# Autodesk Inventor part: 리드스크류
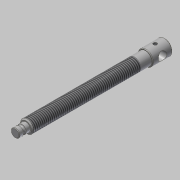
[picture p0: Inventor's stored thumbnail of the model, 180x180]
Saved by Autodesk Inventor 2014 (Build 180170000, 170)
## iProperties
Created: 2019-04
Part Number: 리드스크류
Material: 강철, 연강
Document SubType Name: Modeling
Designer: mduedu
Density: 1 g/cm^3
Appearance: 강철
Author: mduedu
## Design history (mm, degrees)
sketch "스케치1"
  geometry: C1 r 6 at (0, 0); 1 further point
  constraints: 1 centre point, 1 coincident
  dimensions: "d0" = 12 diameter of C1
extrude "돌출1" new body sketch "스케치1" distance "d1" = 110; taper "d2" = 0 deg
sketch "스케치2"
  geometry: C1 r 4 at (0, 0); 1 further point
  constraints: 1 centre point, 1 coincident
  dimensions: "d3" = 8 diameter of C1
extrude "돌출2" join sketch "스케치2" distance "d4" = 10; taper "d5" = 0 deg
sketch "스케치3"
  geometry: C1 r 7 at (0, 0); 1 further point
  constraints: 1 centre point, 1 coincident
  dimensions: "d9" = 14 diameter of C1
extrude "돌출3" join sketch "스케치3" distance "d10" = 18; taper "d11" = 0 deg
feature "스레드1" dims "d12" = 100, "d13" = 0
chamfer "모따기2" distance "d14" = 1; stored, may be unused: second distance "d15" = 2, angle "d16" = 45 deg
chamfer "모따기3" distance "d17" = 0.5; stored, may be unused: second distance "d18" = 2, angle "d19" = 45 deg
chamfer "모따기4" distance "d20" = 0.5; stored, may be unused: second distance "d21" = 2, angle "d22" = 45 deg
sketch "스케치4"
  geometry: L1 (-110, -5)-(-110, 5) reference; L2 (-119.5, 4)-(-119.5, -4) reference; L3 (-119.5, 0)-(-110, 0); C1 r 1.25 at (-115, 4); 1 further point
  constraints: 2 end point, 2 midpoint, 1 centre point
  dimensions: "d23" = 2.5 diameter of C1; "d24" = 5 distance from line of C1.centre L1; "d25" = 4 distance from line of C1.centre L3
revolve "회전1" sketch "스케치4" stored, may be unused: angle "d26" = 90 deg
sketch "스케치5"
  geometry: L1 (0, -6.5)-(0, 6.5) reference; C1 r 4 at (9, 0); 2 further points
  constraints: 1 centre point, 1 horizontal alignment, 1 midpoint
  dimensions: "d27" = 8 diameter of C1; "d28" = 9 distance from line of C1.centre L1
extrude "돌출4" cut sketch "스케치5" stored distance "d29" = 15; taper "d30" = 0 deg
node "작업 평면1"
sketch "스케치6"
  geometry: L1 (0, 6.5)-(0, -6.5) reference; 2 further points
  constraints: 1 horizontal alignment
  dimensions: "d31" = 9 distance from line of point (-9, 0) L1
hole "구멍1" sketch "스케치6" at (-9, 0) diameter "d32" = 3.242; stored, may be unused: countersink angle "d36" = 90 deg, drill point angle "d38" = 118 deg; dims "d33" = 6, "d34" = 4, "d35" = 2, "d37" = 8
node "솔리드1"
